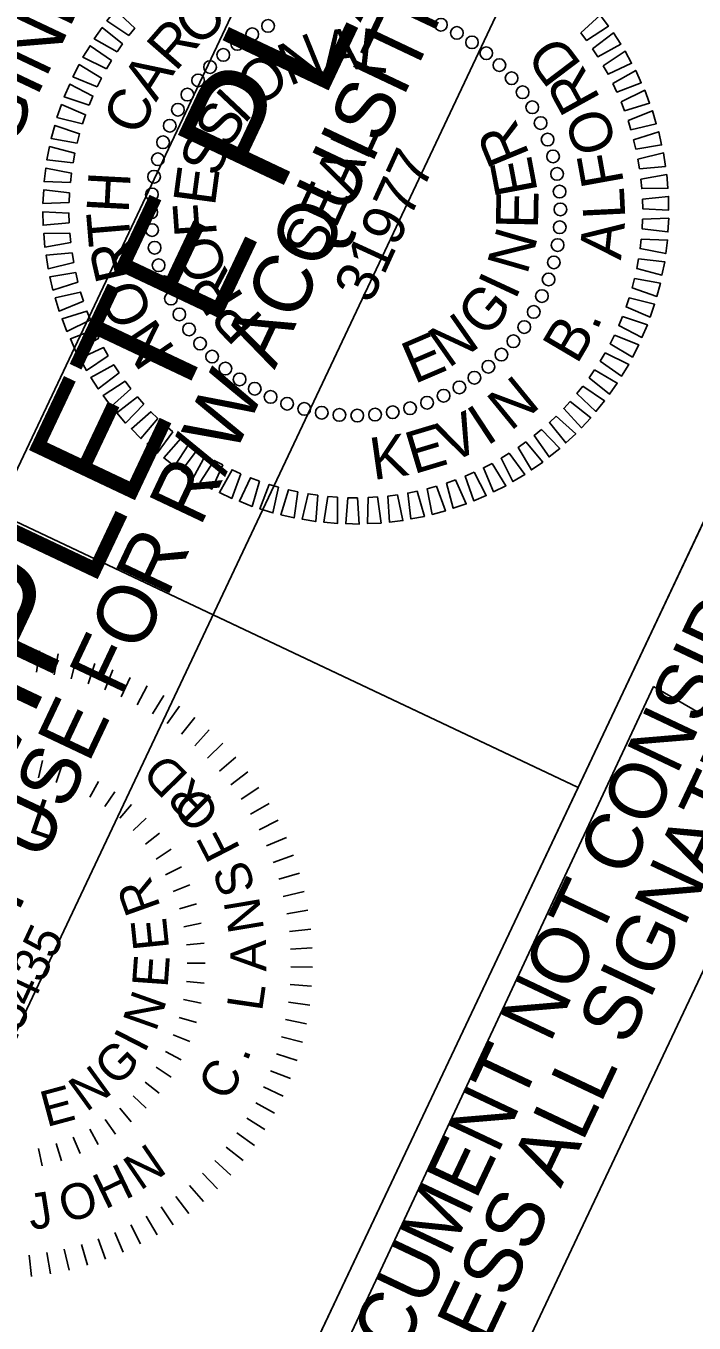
# Model space of a CAD drawing. Extents: x 556536 to 558250, y 505355 to 507347.
# Drawn here: x 557295.8 to 557377.9, y 507100.8 to 507260 of the extents above; entities that cross this region are included whole.
import ezdxf

# ---------------------------------------------------------------- set-up
doc = ezdxf.new("R2010")
doc.units = 0
for name, color, linetype in [('Prop Drainage Structure Catch Basin Grate 840 03G CELL', 7, 'Continuous'), ('Prop Drainage Structure Tops and Inverts LABEL', 7, 'Continuous'), ('Prop Earthen Structure Ditch Flow Line', 7, 'Continuous'), ('Prop Erosion Rip Rap Class B', 7, 'Continuous'), ('Prop Erosion Rip Rap Pad at Outlet CELL', 7, 'Continuous')]:
    doc.layers.add(name, color=color, linetype=linetype)

msp = doc.modelspace()

# ---------------------------------------------------------------- linework, layer by layer
at = {"layer": 'Prop Drainage Structure Catch Basin Grate 840 03G CELL'}
msp.add_lwpolyline([(557798.52, 506240.88), (557748.79, 506156.98), (557718.06, 506089.72), (557705.43, 506089.79), (557646.19, 505968.9), (557731.53, 505869.1), (557643.42, 505687.13), (557512.37, 505750.31), (557008.7, 505860.07), (556630.15, 505965.86), (557185.22, 507140.23), (557323.61, 507073.55), (557372.9, 507178.95), (557443.19, 507138.35), (557473.73, 506971.77), (557393.31, 506960), (557425.46, 506933.59), (557889.73, 506539.36), (557955.03, 506511.13), (557971.08, 506460.75)], close=True, dxfattribs=at)
at = {"layer": 'Prop Drainage Structure Tops and Inverts LABEL'}
msp.add_lwpolyline([(557279.52, 507104.69), (557252.96, 507117.24), (557331.48, 507283.37), (557358.04, 507270.82)], close=True, dxfattribs=at)
at = {"layer": 'Prop Earthen Structure Ditch Flow Line'}
for p, q in [((557320.88, 507076.11), (557406.36, 507256.97)), ((557427.61, 507246.93), (557342.13, 507066.07))]:
    msp.add_line(p, q, dxfattribs=at)
at = {"layer": 'Prop Erosion Rip Rap Class B'}
msp.add_line((557261.92, 507214.64), (557363.59, 507166.59), dxfattribs=at)
for points in [[(557261.92, 507214.64), (557304.66, 507305.05), (557406.37, 507256.98), (557363.64, 507166.57)], [(557219.17, 507124.19), (557261.92, 507214.64), (557363.64, 507166.57), (557320.88, 507076.11)]]:
    msp.add_lwpolyline(points, close=True, dxfattribs=at)
at = {"layer": 'Prop Erosion Rip Rap Pad at Outlet CELL'}
for p, q in [((557297.49, 507183.34), (557297.14, 507180.73)), ((557299.8, 507182.96), (557299.29, 507180.37)), ((557302.07, 507182.44), (557301.41, 507179.89)), ((557304.31, 507181.78), (557303.5, 507179.28)), ((557306.51, 507181), (557305.55, 507178.54)), ((557308.66, 507180.08), (557307.55, 507177.68)), ((557310.75, 507179.03), (557309.5, 507176.71)), ((557312.77, 507177.85), (557311.38, 507175.61)), ((557314.72, 507176.56), (557313.2, 507174.41)), ((557316.58, 507175.16), (557314.93, 507173.1)), ((557318.36, 507173.64), (557316.59, 507171.68)), ((557320.04, 507172.01), (557318.15, 507170.17)), ((557297.86, 507169.89), (557297.38, 507167.75)), ((557300.24, 507169.24), (557299.56, 507167.16)), ((557321.62, 507170.29), (557319.63, 507168.57)), ((557302.54, 507168.37), (557301.66, 507166.36)), ((557304.75, 507167.28), (557303.68, 507165.36)), ((557323.1, 507168.48), (557321, 507166.88)), ((557305.53, 507164.21), (557306.77, 507166.03)), ((557324.46, 507166.58), (557322.27, 507165.11)), ((557308.8, 507164.48), (557307.38, 507162.8)), ((557325.7, 507164.6), (557323.43, 507163.27)), ((557310.6, 507162.8), (557309.03, 507161.27)), ((557326.82, 507162.55), (557324.47, 507161.36)), ((557312.23, 507160.96), (557310.52, 507159.59)), ((557327.82, 507160.44), (557325.4, 507159.39)), ((557313.68, 507158.97), (557311.84, 507157.76)), ((557328.69, 507158.27), (557326.21, 507157.36)), ((557314.93, 507156.84), (557312.98, 507155.82)), ((557329.42, 507156.05), (557326.9, 507155.3)), ((557315.96, 507154.61), (557313.93, 507153.78)), ((557330.02, 507153.79), (557327.45, 507153.19)), ((557316.78, 507152.29), (557314.68, 507151.66)), ((557330.48, 507151.5), (557327.89, 507151.06)), ((557317.37, 507149.89), (557315.22, 507149.47)), ((557330.81, 507149.19), (557328.19, 507148.9)), ((557317.73, 507147.45), (557315.54, 507147.24)), ((557330.99, 507146.86), (557328.35, 507146.73)), ((557317.84, 507144.99), (557315.65, 507144.99)), ((557331.03, 507144.52), (557328.39, 507144.56)), ((557317.73, 507142.53), (557315.54, 507142.74)), ((557330.93, 507142.18), (557328.3, 507142.38)), ((557317.37, 507140.09), (557315.21, 507140.52)), ((557330.69, 507139.86), (557328.08, 507140.22)), ((557316.78, 507137.7), (557314.67, 507138.33)), ((557330.31, 507137.55), (557327.73, 507138.07)), ((557315.96, 507135.38), (557313.93, 507136.21)), ((557329.79, 507135.28), (557327.24, 507135.94)), ((557314.92, 507133.14), (557312.98, 507134.16)), ((557329.14, 507133.04), (557326.63, 507133.85)), ((557313.67, 507131.02), (557311.83, 507132.23)), ((557328.35, 507130.84), (557325.89, 507131.8)), ((557310.5, 507130.39), (557312.22, 507129.02)), ((557327.43, 507128.69), (557325.03, 507129.8)), ((557310.59, 507127.19), (557309.02, 507128.72)), ((557326.38, 507126.6), (557324.06, 507127.85)), ((557306.83, 507124.01), (557305.58, 507125.82)), ((557308.78, 507125.51), (557307.37, 507127.19)), ((557325.2, 507124.58), (557322.96, 507125.97)), ((557304.73, 507122.72), (557303.67, 507124.63)), ((557323.91, 507122.63), (557321.76, 507124.16)), ((557300.22, 507120.75), (557299.54, 507122.84)), ((557302.52, 507121.62), (557301.65, 507123.64)), ((557297.85, 507120.1), (557297.37, 507122.25)), ((557322.51, 507120.77), (557320.45, 507122.42)), ((557320.99, 507118.99), (557319.03, 507120.76)), ((557319.36, 507117.31), (557317.52, 507119.2)), ((557315.83, 507114.26), (557314.23, 507116.35)), ((557317.64, 507115.73), (557315.92, 507117.72)), ((557313.93, 507112.89), (557312.46, 507115.08)), ((557311.95, 507111.65), (557310.62, 507113.92)), ((557307.79, 507109.53), (557306.74, 507111.95)), ((557309.9, 507110.53), (557308.71, 507112.88)), ((557301.14, 507107.33), (557300.54, 507109.9)), ((557303.4, 507107.93), (557302.65, 507110.46)), ((557305.62, 507108.67), (557304.71, 507111.14)), ((557296.54, 507106.54), (557296.25, 507109.17)), ((557298.85, 507106.87), (557298.41, 507109.47))]:
    msp.add_line(p, q, dxfattribs=at)
for points in [[(557308.46, 507258.85), (557305.79, 507260.67), (557306.86, 507261.96), (557309.2, 507259.78)], [(557363.97, 507259.2), (557366.38, 507261.35), (557367.37, 507260.01), (557364.69, 507258.26)], [(557307.03, 507256.85), (557304.24, 507258.48), (557305.21, 507259.84), (557307.7, 507257.83)], [(557365.42, 507257.22), (557367.98, 507259.2), (557368.88, 507257.79), (557366.08, 507256.24)], [(557305.74, 507254.76), (557302.84, 507256.19), (557303.72, 507257.62), (557306.34, 507255.78)], [(557366.74, 507255.14), (557369.43, 507256.94), (557370.22, 507255.47), (557367.33, 507254.12)], [(557304.6, 507252.58), (557301.61, 507253.81), (557302.38, 507255.29), (557305.12, 507253.65)], [(557367.91, 507252.98), (557370.72, 507254.59), (557371.41, 507253.06), (557368.42, 507251.92)], [(557303.62, 507250.33), (557300.54, 507251.34), (557301.22, 507252.88), (557304.06, 507251.43)], [(557368.92, 507250.74), (557371.83, 507252.15), (557372.42, 507250.58), (557369.36, 507249.64)], [(557302.79, 507248.02), (557299.65, 507248.81), (557300.22, 507250.39), (557303.16, 507249.14)], [(557369.78, 507248.44), (557372.78, 507249.64), (557373.25, 507248.03), (557370.14, 507247.31)], [(557302.13, 507245.65), (557298.94, 507246.23), (557299.4, 507247.84), (557302.42, 507246.8)], [(557370.47, 507246.08), (557373.55, 507247.06), (557373.91, 507245.43), (557370.75, 507244.93)], [(557301.63, 507243.24), (557298.42, 507243.59), (557298.75, 507245.23), (557301.84, 507244.41)], [(557371, 507243.68), (557374.14, 507244.45), (557374.38, 507242.79), (557371.2, 507242.51)], [(557301.3, 507240.81), (557298.07, 507240.93), (557298.29, 507242.59), (557301.43, 507241.98)], [(557371.35, 507241.25), (557374.54, 507241.79), (557374.67, 507240.12), (557371.47, 507240.07)], [(557301.15, 507238.35), (557297.92, 507238.25), (557298.02, 507239.92), (557301.19, 507239.54)], [(557371.54, 507238.79), (557374.76, 507239.12), (557374.77, 507237.44), (557371.58, 507237.61)], [(557301.16, 507235.89), (557297.95, 507235.57), (557297.93, 507237.24), (557301.13, 507237.08)], [(557371.56, 507236.34), (557374.79, 507236.43), (557374.68, 507234.76), (557371.51, 507235.15)], [(557301.35, 507233.44), (557298.16, 507232.9), (557298.04, 507234.57), (557301.23, 507234.62)], [(557371.4, 507233.88), (557374.63, 507233.76), (557374.41, 507232.1), (557371.27, 507232.71)], [(557301.71, 507231.01), (557298.57, 507230.24), (557298.32, 507231.9), (557301.51, 507232.18)], [(557371.07, 507231.45), (557374.29, 507231.09), (557373.95, 507229.45), (557370.86, 507230.28)], [(557302.23, 507228.61), (557299.15, 507227.62), (557298.79, 507229.26), (557301.95, 507229.76)], [(557370.58, 507229.04), (557373.76, 507228.46), (557373.31, 507226.85), (557370.29, 507227.89)], [(557302.93, 507226.25), (557299.92, 507225.05), (557299.45, 507226.66), (557302.56, 507227.38)], [(557369.91, 507226.67), (557373.05, 507225.88), (557372.48, 507224.3), (557369.54, 507225.55)], [(557303.78, 507223.95), (557300.87, 507222.54), (557300.29, 507224.11), (557303.34, 507225.05)], [(557369.09, 507224.36), (557372.16, 507223.34), (557371.49, 507221.81), (557368.64, 507223.26)], [(557304.79, 507221.71), (557301.99, 507220.1), (557301.3, 507221.63), (557304.28, 507222.77)], [(557368.1, 507222.1), (557371.09, 507220.88), (557370.32, 507219.4), (557367.58, 507221.04)], [(557305.96, 507219.54), (557303.27, 507217.75), (557302.48, 507219.22), (557305.37, 507220.57)], [(557366.96, 507219.93), (557369.86, 507218.5), (557368.98, 507217.07), (557366.37, 507218.9)], [(557307.28, 507217.47), (557304.72, 507215.49), (557303.82, 507216.9), (557306.62, 507218.45)], [(557365.67, 507217.83), (557368.46, 507216.2), (557367.49, 507214.84), (557365.01, 507216.86)], [(557308.74, 507215.49), (557306.32, 507213.33), (557305.33, 507214.68), (557308.01, 507216.42)], [(557364.24, 507215.84), (557366.91, 507214.02), (557365.84, 507212.73), (557363.51, 507214.91)], [(557310.33, 507213.61), (557308.07, 507211.3), (557306.99, 507212.57), (557309.54, 507214.5)], [(557362.67, 507213.94), (557365.21, 507211.94), (557364.05, 507210.73), (557361.88, 507213.07)], [(557312.05, 507211.86), (557309.96, 507209.39), (557308.79, 507210.59), (557311.2, 507212.68)], [(557360.97, 507212.16), (557363.37, 507209.99), (557362.13, 507208.86), (557360.12, 507211.35)], [(557313.88, 507210.22), (557311.97, 507207.62), (557310.72, 507208.73), (557312.98, 507210.99)], [(557359.16, 507210.51), (557361.39, 507208.17), (557360.08, 507207.13), (557358.25, 507209.75)], [(557315.83, 507208.72), (557314.1, 507205.99), (557312.78, 507207.01), (557314.87, 507209.42)], [(557357.23, 507208.98), (557359.3, 507206.5), (557357.92, 507205.55), (557356.27, 507208.29)], [(557317.88, 507207.36), (557316.35, 507204.51), (557314.95, 507205.44), (557316.87, 507207.99)], [(557355.2, 507207.59), (557357.09, 507204.97), (557355.65, 507204.12), (557354.19, 507206.97)], [(557320.01, 507206.15), (557318.68, 507203.2), (557317.23, 507204.02), (557318.97, 507206.7)], [(557322.23, 507205.08), (557321.11, 507202.05), (557319.6, 507202.77), (557321.15, 507205.57)], [(557353.08, 507206.35), (557354.78, 507203.6), (557353.28, 507202.86), (557352.03, 507205.8)], [(557324.51, 507204.17), (557323.61, 507201.07), (557322.05, 507201.69), (557323.4, 507204.58)], [(557348.6, 507204.33), (557349.91, 507201.37), (557348.32, 507200.84), (557347.49, 507203.93)], [(557350.88, 507205.26), (557352.38, 507202.4), (557350.83, 507201.76), (557349.79, 507204.78)], [(557326.86, 507203.43), (557326.17, 507200.27), (557324.57, 507200.78), (557325.72, 507203.76)], [(557329.25, 507202.85), (557328.78, 507199.65), (557327.15, 507200.04), (557328.09, 507203.1)], [(557331.67, 507202.44), (557331.43, 507199.21), (557329.78, 507199.49), (557330.5, 507202.61)], [(557334.11, 507202.2), (557334.1, 507198.96), (557332.43, 507199.13), (557332.93, 507202.28)], [(557339.03, 507202.23), (557339.46, 507199.02), (557337.79, 507198.95), (557337.85, 507202.15)], [(557341.47, 507202.5), (557342.13, 507199.33), (557340.47, 507199.15), (557340.3, 507202.34)], [(557343.89, 507202.94), (557344.77, 507199.83), (557343.12, 507199.53), (557342.73, 507202.7)], [(557346.27, 507203.55), (557347.36, 507200.51), (557345.74, 507200.09), (557345.13, 507203.23)], [(557336.57, 507202.13), (557336.78, 507198.9), (557335.11, 507198.95), (557335.39, 507202.13)]]:
    msp.add_lwpolyline(points, close=True, dxfattribs=at)
for centre in [(557323.64, 507259.02), (557325.57, 507260.04), (557346.81, 507260.19), (557348.76, 507259.19), (557321.8, 507257.83), (557350.62, 507258.03), (557320.07, 507256.48), (557352.37, 507256.7), (557318.46, 507254.99), (557353.99, 507255.23), (557316.99, 507253.36), (557355.49, 507253.63), (557315.67, 507251.61), (557356.83, 507251.9), (557314.5, 507249.76), (557358.02, 507250.06), (557313.51, 507247.8), (557359.05, 507248.12), (557359.9, 507246.1), (557312.68, 507245.77), (557312.04, 507243.68), (557360.58, 507244.02), (557311.58, 507241.53), (557361.06, 507241.88), (557361.37, 507239.71), (557311.31, 507239.36), (557311.23, 507237.17), (557361.48, 507237.52), (557311.34, 507234.98), (557361.4, 507235.33), (557311.64, 507232.81), (557361.13, 507233.15), (557312.13, 507230.67), (557360.67, 507231.01), (557312.8, 507228.59), (557360.02, 507228.92), (557359.2, 507226.88), (557313.65, 507226.57), (557314.68, 507224.63), (557358.2, 507224.93), (557315.87, 507222.79), (557357.03, 507223.08), (557317.22, 507221.06), (557355.71, 507221.33), (557318.71, 507219.45), (557354.24, 507219.7), (557320.33, 507217.98), (557352.64, 507218.21), (557322.08, 507216.66), (557350.91, 507216.86), (557323.94, 507215.5), (557325.89, 507214.5), (557347.13, 507214.65), (557349.07, 507215.67), (557327.92, 507213.67), (557330.02, 507213.03), (557332.16, 507212.57), (557340.89, 507212.63), (557343.02, 507213.12), (557345.11, 507213.79), (557334.34, 507212.3), (557336.53, 507212.22), (557338.72, 507212.33)]:
    msp.add_circle(centre, 0.777, dxfattribs=at)

# ---------------------------------------------------------------- texts
at = {"layer": 'Prop Drainage Structure Tops and Inverts LABEL'}
for s, height, p in [('INCOMPLETE PLANS', 14.4, (557271.07, 507121.08)), ('DO NOT USE FOR R/W ACQUISITION', 7.2, (557280.66, 507121.04))]:
    msp.add_text(s, height=height, rotation=64.7021, dxfattribs=at).set_placement(p)
at = {"layer": 'Prop Earthen Structure Ditch Flow Line'}
for s, p in [('UNLESS ALL SIGNATURES COMPLETED', (557344.39, 507081.06)), ('DOCUMENT NOT CONSIDERED FINAL', (557335.96, 507083.8))]:
    msp.add_text(s, height=7, rotation=64.7021, dxfattribs=at).set_placement(p)
at = {"layer": 'Prop Erosion Rip Rap Class B'}
for s, p in [('HYDRAULICS', (557279.05, 507231.45)), ('ENGINEER', (557288.48, 507232.81))]:
    msp.add_text(s, height=7, rotation=64.7021, dxfattribs=at).set_placement(p)
at = {"layer": 'Prop Erosion Rip Rap Pad at Outlet CELL'}
for s, height, rotation, p in [('O', 5.18, 40.5993, (557316.85, 507257.31)), ('R', 5.18, 48.8079, (557314.2, 507254.32)), ('A', 5.18, 7.0901, (557332.43, 507254.21)), ('L', 5.18, 353.7542, (557336.42, 507254.66)), ('N', 5.18, 22.1402, (557328.18, 507252.62)), ('D', 5.18, 127.0991, (557364.21, 507255.26)), ('A', 5.18, 57.8554, (557311.81, 507250.62)), ('O', 5.18, 37.949, (557324.33, 507249.81)), ('R', 5.18, 118.8904, (557366.48, 507251.1)), ('C', 5.18, 67.3604, (557309.95, 507246.39)), ('I', 5.18, 46.7044, (557322.57, 507247.84)), ('S', 5.18, 58.6634, (557320.7, 507244.75)), ('R', 5.18, 112.4416, (557357.75, 507244.22)), ('O', 5.18, 108.1653, (557368.51, 507245.26)), ('SEAL', 5.181, 65.3986, (557331.95, 507230.84)), ('S', 5.18, 70.6223, (557319.5, 507241.35)), ('31977', 5.181, 65.3986, (557338.18, 507225.79)), ('E', 5.18, 100.6793, (557358.71, 507239.71)), ('F', 5.18, 100.2426, (557369.3, 507240.75)), ('E', 5.18, 82.3846, (557319.04, 507237.83)), ('H', 5.18, 86.9996, (557308.45, 507236.99)), ('E', 5.18, 88.9171, (557358.72, 507235.11)), ('L', 5.18, 92.7775, (557369.46, 507236.44)), ('F', 5.18, 94.0625, (557319.3, 507234.32)), ('T', 5.18, 94.7889, (557308.75, 507233.21)), ('A', 5.18, 83.73, (557368.91, 507231.24)), ('N', 5.18, 73.867, (557357.37, 507229.38)), ('R', 5.18, 102.9975, (557309.63, 507229.31)), ('O', 5.18, 109.8713, (557320.77, 507229.78)), ('R', 5.18, 121.9707, (557322.7, 507226.69)), ('I', 5.18, 65.1116, (557355.91, 507226.27)), ('O', 5.18, 113.7227, (557311.59, 507224.48)), ('G', 5.18, 50.0615, (557352.37, 507221.57)), ('P', 5.18, 133.733, (557325.16, 507224.13)), ('N', 5.18, 35.0115, (557347.72, 507217.95)), ('N', 5.18, 123.9331, (557314.26, 507220.3)), ('B', 5.18, 59.4186, (557363.51, 507218.38)), ('.', 5.18, 67.7607, (557365.97, 507222.52)), ('E', 5.18, 23.2492, (557343.53, 507216.04)), ('N', 5.18, 39.3218, (557355.34, 507210.21)), ('I', 5.18, 33.3819, (557352.43, 507208.39)), ('V', 5.18, 24.6966, (557347.87, 507206.29)), ('E', 5.18, 16.7167, (557343.45, 507204.99)), ('K', 5.18, 8.0124, (557338.47, 507204.29)), (' RD', 4.391, 134.7314, (557320.11, 507163.87)), ('O ', 4.391, 126.0587, (557319.86, 507163.28)), ('L', 4.39, 340.9296, (557295.98, 507161.16)), ('F', 4.39, 117.2661, (557322.26, 507159.01)), ('S', 4.39, 108.3834, (557324.09, 507154.13)), ('R', 4.39, 109.6239, (557312.43, 507151.88)), ('N', 4.39, 99.5008, (557325.12, 507149.12)), ('15435', 4.391, 65.059, (557293.73, 507133.51)), ('E', 4.39, 95.8528, (557313.44, 507146.8)), ('A', 4.39, 90.6782, (557325.37, 507143.97)), ('E', 4.39, 85.8669, (557313.24, 507141.92)), ('L', 4.39, 81.6756, (557324.83, 507138.99)), ('N', 4.39, 70.4749, (557311.78, 507136.47)), ('I', 4.39, 62.8452, (557310.39, 507133.83)), ('G', 4.39, 44.7504, (557306.91, 507129.68)), ('.', 4.39, 68.8913, (557323.01, 507132.79)), ('N', 4.39, 35.9842, (557303.23, 507126.65)), ('C', 4.39, 61.149, (557320.61, 507127.89)), ('E', 4.39, 15.1291, (557298.36, 507124.85)), ('N', 4.39, 34.3812, (557309.87, 507117)), ('H', 4.39, 25.7086, (557305.54, 507114.72)), ('O', 4.39, 17.0658, (557300.68, 507113.03)), ('J', 4.39, 8.994, (557296.45, 507112.23))]:
    msp.add_text(s, height=height, rotation=rotation, dxfattribs=at).set_placement(p)

doc.saveas('drawing.dxf')
